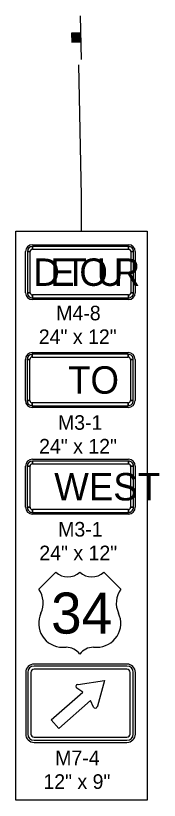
# Model space of a CAD drawing. Extents: x 10133 to 81668, y 6132 to 11018.
# Drawn here: x 14795.1 to 14873.8, y 6132.4 to 6562.7 of the extents above; entities that cross this region are included whole.
import ezdxf

# ---------------------------------------------------------------- set-up
doc = ezdxf.new("R2010")
doc.units = 0
for name, color, linetype in [('dsnTextFinalPlan', 7, 'Continuous'), ('Level 10', 7, 'Continuous'), ('Level 4', 7, 'Continuous'), ('Level 5', 7, 'Continuous')]:
    doc.layers.add(name, color=color, linetype=linetype)

msp = doc.modelspace()

# ---------------------------------------------------------------- linework, layer by layer
at = {"layer": 'dsnTextFinalPlan'}
for p, q in [((14830.47, 6562.73), (14831.07, 6538.74)), ((14826.06, 6553.14), (14826.18, 6548.27)), ((14826.46, 6548.27), (14826.34, 6553.15)), ((14826.54, 6553.15), (14826.66, 6548.28)), ((14826.94, 6548.29), (14826.81, 6553.16)), ((14827.01, 6553.17), (14827.12, 6548.29)), ((14827.49, 6548.3), (14827.39, 6553.18)), ((14827.57, 6553.18), (14827.69, 6548.31)), ((14828.06, 6548.31), (14827.94, 6553.19)), ((14828.27, 6553.2), (14828.39, 6548.32)), ((14828.67, 6548.33), (14828.57, 6553.21)), ((14828.74, 6553.21), (14828.87, 6548.33)), ((14829.1, 6548.34), (14828.97, 6553.22)), ((14829.27, 6553.22), (14829.39, 6548.35)), ((14829.57, 6548.35), (14829.45, 6553.23)), ((14829.64, 6553.23), (14829.77, 6548.36)), ((14829.99, 6548.36), (14829.87, 6553.24)), ((14830.1, 6553.24), (14830.22, 6548.37)), ((14830.47, 6548.37), (14830.35, 6553.25)), ((14856.11, 6207.12), (14805.14, 6207.12)), ((14800.56, 6202.54), (14800.56, 6168.75)), ((14860.69, 6168.75), (14860.69, 6202.54)), ((14805.14, 6164.17), (14856.11, 6164.17))]:
    msp.add_line(p, q, dxfattribs=at)
for points in [[(14830.75, 6548.38), (14830.63, 6553.29), (14825.72, 6553.17), (14825.84, 6548.26)], [(14795.09, 6444.61), (14867.16, 6444.61), (14867.16, 6132.39), (14795.09, 6132.39)], [(14795.09, 6444.61), (14867.16, 6444.61), (14867.16, 6132.39), (14795.09, 6132.39)]]:
    msp.add_lwpolyline(points, close=True, dxfattribs=at)
for points in [[(14831.13, 6444.61), (14831.13, 6463.96), (14829.69, 6535.81)], [(14829.41, 6195.98), (14843.77, 6198.05), (14839.92, 6184.07)], [(14837.7, 6183.56), (14836.08, 6187.07), (14818.75, 6171.79), (14814.6, 6176.5), (14831.92, 6191.78), (14828.63, 6193.81)]]:
    msp.add_lwpolyline(points, dxfattribs=at)
for centre, radius, start, end in [((14805.14, 6202.54), 4.58, 90, 180), ((14856.11, 6202.54), 4.58, 360, 90), ((14829.25, 6194.79), 1.16, 98.0346, 237.3927), ((14812.88, 6310.76), 115.96, 278.0346, 278.1951), ((14838.73, 6184.05), 1.14, 205.4546, 344.7341), ((14951.7, 6153.21), 115.96, 164.5667, 164.7341), ((14805.14, 6168.75), 4.58, 180, 270), ((14856.11, 6168.75), 4.58, 270, 0)]:
    msp.add_arc(centre, radius, start, end, dxfattribs=at)
at = {"layer": 'Level 10'}
for p, q in [((14804.3, 6437.1), (14856.91, 6437.1)), ((14804.3, 6434.59), (14804.3, 6436.16)), ((14856.91, 6436.16), (14856.91, 6434.59)), ((14800.54, 6410.79), (14800.54, 6433.34)), ((14801.48, 6433.34), (14803.05, 6433.34)), ((14858.17, 6433.34), (14859.73, 6433.34)), ((14860.67, 6433.34), (14860.67, 6410.79)), ((14803.05, 6410.79), (14801.48, 6410.79)), ((14804.3, 6407.97), (14804.3, 6409.54)), ((14856.91, 6409.54), (14856.91, 6407.97)), ((14859.73, 6410.79), (14858.17, 6410.79)), ((14856.91, 6407.03), (14804.3, 6407.03)), ((14804.14, 6377.96), (14856.75, 6377.96)), ((14800.38, 6351.65), (14800.38, 6374.2)), ((14801.32, 6374.2), (14802.89, 6374.2)), ((14804.14, 6375.45), (14804.14, 6377.02)), ((14856.75, 6377.02), (14856.75, 6375.45)), ((14858, 6374.2), (14859.57, 6374.2)), ((14860.51, 6374.2), (14860.51, 6351.65)), ((14802.89, 6351.65), (14801.32, 6351.65)), ((14804.14, 6348.83), (14804.14, 6350.4)), ((14856.75, 6347.89), (14804.14, 6347.89)), ((14856.75, 6350.4), (14856.75, 6348.83)), ((14859.57, 6351.65), (14858, 6351.65)), ((14804.24, 6319.41), (14856.86, 6319.41)), ((14804.24, 6316.9), (14804.24, 6318.47)), ((14856.86, 6318.47), (14856.86, 6316.9)), ((14800.49, 6293.1), (14800.49, 6315.65)), ((14801.43, 6315.65), (14802.99, 6315.65)), ((14858.11, 6315.65), (14859.68, 6315.65)), ((14860.61, 6315.65), (14860.61, 6293.1)), ((14802.99, 6293.1), (14801.43, 6293.1)), ((14804.24, 6290.28), (14804.24, 6291.85)), ((14856.86, 6291.85), (14856.86, 6290.28)), ((14859.68, 6293.1), (14858.11, 6293.1)), ((14856.86, 6289.34), (14804.24, 6289.34)), ((14856.11, 6205.97), (14805.14, 6205.97)), ((14801.71, 6202.54), (14801.71, 6168.75)), ((14803.43, 6202.54), (14803.43, 6168.75)), ((14856.11, 6204.26), (14805.14, 6204.26)), ((14857.83, 6168.75), (14857.83, 6202.54)), ((14859.55, 6168.75), (14859.55, 6202.54)), ((14805.14, 6167.03), (14856.11, 6167.03)), ((14805.14, 6165.32), (14856.11, 6165.32))]:
    msp.add_line(p, q, dxfattribs=at)
for points in [[(14856.91, 6436.16), (14804.3, 6436.16), (14804.3, 6434.59), (14856.91, 6434.59), (14856.91, 6436.16)], [(14801.48, 6433.34), (14801.48, 6410.79), (14803.05, 6410.79), (14803.05, 6433.34), (14801.48, 6433.34)], [(14859.73, 6410.79), (14859.73, 6433.34), (14858.17, 6433.34), (14858.17, 6410.79), (14859.73, 6410.79)], [(14804.3, 6407.97), (14856.91, 6407.97), (14856.91, 6409.54), (14804.3, 6409.54), (14804.3, 6407.97)], [(14801.32, 6374.2), (14801.32, 6351.65), (14802.89, 6351.65), (14802.89, 6374.2), (14801.32, 6374.2)], [(14856.75, 6377.02), (14804.14, 6377.02), (14804.14, 6375.45), (14856.75, 6375.45), (14856.75, 6377.02)], [(14859.57, 6351.65), (14859.57, 6374.2), (14858, 6374.2), (14858, 6351.65), (14859.57, 6351.65)], [(14804.14, 6348.83), (14856.75, 6348.83), (14856.75, 6350.4), (14804.14, 6350.4), (14804.14, 6348.83)], [(14856.86, 6318.47), (14804.24, 6318.47), (14804.24, 6316.9), (14856.86, 6316.9), (14856.86, 6318.47)], [(14801.43, 6315.65), (14801.43, 6293.1), (14802.99, 6293.1), (14802.99, 6315.65), (14801.43, 6315.65)], [(14859.68, 6293.1), (14859.68, 6315.65), (14858.11, 6315.65), (14858.11, 6293.1), (14859.68, 6293.1)], [(14804.24, 6290.28), (14856.86, 6290.28), (14856.86, 6291.85), (14804.24, 6291.85), (14804.24, 6290.28)]]:
    msp.add_lwpolyline(points, close=True, dxfattribs=at)
for centre, radius, start, end in [((14804.3, 6433.34), 3.76, 90, 180), ((14804.3, 6433.34), 2.82, 90.0002, 179.9998), ((14804.3, 6433.34), 1.25, 90.0002, 179.9998), ((14856.91, 6433.34), 3.76, 0, 90), ((14856.91, 6433.34), 2.82, 0, 90.0002), ((14856.91, 6433.34), 1.25, 0, 90.0002), ((14804.3, 6410.79), 3.76, 180, 270), ((14804.3, 6410.79), 2.82, 179.9998, 270.0001), ((14804.3, 6410.79), 1.25, 179.9998, 270.0001), ((14856.91, 6410.79), 2.82, 270.0001, 0.0003), ((14856.91, 6410.79), 1.25, 270.0001, 0.0003), ((14856.91, 6410.79), 3.76, 270, 359.9911), ((14804.14, 6374.2), 3.76, 90, 180), ((14856.75, 6374.2), 3.76, 0, 90), ((14804.14, 6374.2), 2.82, 90.0002, 179.9998), ((14804.14, 6374.2), 1.25, 90.0002, 179.9998), ((14856.75, 6374.2), 2.82, 0, 90.0002), ((14856.75, 6374.2), 1.25, 0, 90.0002), ((14804.14, 6351.65), 3.76, 180, 270), ((14804.14, 6351.65), 2.82, 179.9998, 270.0001), ((14804.14, 6351.65), 1.25, 179.9998, 270.0001), ((14856.75, 6351.65), 2.82, 270.0001, 0.0003), ((14856.75, 6351.65), 1.25, 270.0001, 0.0003), ((14856.75, 6351.65), 3.76, 270, 359.9911), ((14804.24, 6315.65), 3.76, 90, 180), ((14804.24, 6315.65), 2.82, 90.0002, 179.9998), ((14856.86, 6315.65), 3.76, 0, 90), ((14856.86, 6315.65), 2.82, 0, 90.0002), ((14804.24, 6315.65), 1.25, 90.0002, 179.9998), ((14856.86, 6315.65), 1.25, 0, 90.0002), ((14804.24, 6293.1), 3.76, 180, 270), ((14804.24, 6293.1), 2.82, 179.9998, 270.0001), ((14804.24, 6293.1), 1.25, 179.9998, 270.0001), ((14856.86, 6293.1), 2.82, 270.0001, 0.0003), ((14856.86, 6293.1), 1.25, 270.0001, 0.0003), ((14856.86, 6293.1), 3.76, 270, 359.9911), ((14805.14, 6202.54), 3.44, 90, 180), ((14856.11, 6202.54), 3.44, 0, 90), ((14805.14, 6202.54), 1.72, 90, 180), ((14856.11, 6202.54), 1.72, 0, 90), ((14805.14, 6168.75), 3.44, 180, 270), ((14805.14, 6168.75), 1.72, 180, 270), ((14856.11, 6168.75), 3.44, 270, 360), ((14856.11, 6168.75), 1.72, 270, 0)]:
    msp.add_arc(centre, radius, start, end, dxfattribs=at)
at = {"layer": 'Level 4'}
for p, q in [((14817.08, 6257.57), (14807.7, 6248.2)), ((14817.08, 6257.57), (14807.7, 6248.2)), ((14852.7, 6248.2), (14843.33, 6257.57)), ((14852.7, 6248.2), (14843.33, 6257.57)), ((14820.83, 6216.32), (14822.7, 6216.32)), ((14820.83, 6216.32), (14822.7, 6216.32)), ((14837.7, 6216.32), (14839.58, 6216.32)), ((14837.7, 6216.32), (14839.58, 6216.32))]:
    msp.add_line(p, q, dxfattribs=at)
for centre, radius, start, end in [((14823.64, 6264.27), 9.38, 225.5729, 314.4272), ((14823.64, 6264.27), 9.38, 225.5729, 314.4272), ((14836.77, 6264.27), 9.38, 225.5729, 314.4272), ((14836.77, 6264.27), 9.38, 225.5729, 314.4272), ((14797.04, 6240.55), 13.13, 334.9895, 35.6629), ((14797.04, 6240.55), 13.13, 334.9895, 35.6629), ((14863.37, 6240.55), 13.13, 144.3372, 205.01), ((14863.37, 6240.55), 13.13, 144.3372, 205.01), ((14820.83, 6229.45), 13.13, 154.9897, 270.0001), ((14820.83, 6229.45), 13.13, 154.9897, 270.0001), ((14839.58, 6229.45), 13.13, 270.0001, 25.0104), ((14839.58, 6229.45), 13.13, 270.0001, 25.0104), ((14822.7, 6206.95), 9.38, 36.8699, 90.0002), ((14822.7, 6206.95), 9.38, 36.8699, 90.0002), ((14837.7, 6206.95), 9.38, 90.0002, 143.13), ((14837.7, 6206.95), 9.38, 90.0002, 143.13)]:
    msp.add_arc(centre, radius, start, end, dxfattribs=at)

# ---------------------------------------------------------------- texts
at = {"layer": 'Level 10'}
for s, height, p in [('D', 15.03, (14804.79, 6414.55)), ('E', 15.03, (14814.02, 6414.55)), ('T', 15.03, (14821.8, 6414.55)), ('O', 15.03, (14830.01, 6414.55)), ('U', 15.03, (14839.6, 6414.55)), ('R', 15.03, (14848.84, 6414.55)), ('TO', 15.032, (14823.8, 6355.41)), ('WEST', 15.032, (14816.22, 6296.86))]:
    msp.add_text(s, height=height, dxfattribs=at).set_placement(p)
at = {"layer": 'Level 4'}
msp.add_text('34', height=22.5, dxfattribs=at).set_placement((14814.5, 6223.82))
msp.add_text('34', height=22.5, dxfattribs=at).set_placement((14814.5, 6223.82))
at = {"layer": 'Level 5'}
for s, p in [('M4-8', (14817.31, 6395.65)), ('24" x 12"', (14807.76, 6382.65)), ('M3-1', (14818.26, 6335.6)), ('24" x 12"', (14807.93, 6322.6)), ('M3-1', (14818.37, 6277.05)), ('24" x 12"', (14808.04, 6264.05)), ('M7-4', (14816.74, 6151.66)), ('12" x 9"', (14810.27, 6138.66))]:
    msp.add_text(s, height=8, dxfattribs=at).set_placement(p)

doc.saveas('drawing.dxf')
